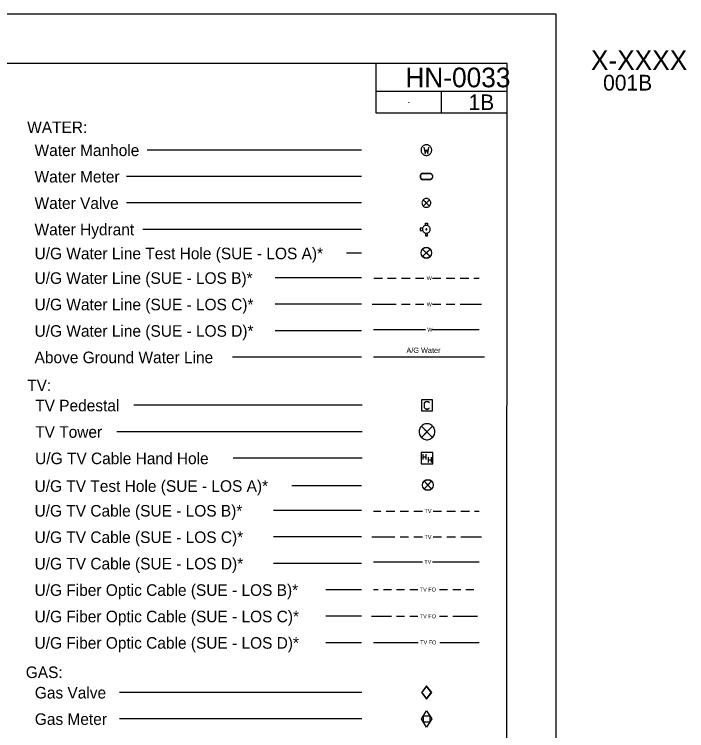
# Model space of a CAD drawing. Extents: x 0 to 3, y 0 to 1.83.
# Drawn here: x 2.143 to 3, y 0.922 to 1.833 of the extents above; entities that cross this region are included whole.
import ezdxf

# ---------------------------------------------------------------- set-up
doc = ezdxf.new("R2010")
doc.units = 0
for name, color, linetype in [('Exist Utilities TV Test Hole SUE LOS A CELL', 7, 'Continuous'), ('Old_Level_2', 7, 'Continuous'), ('Sheet_Plan', 7, 'Continuous'), ('Sheet_Symbology', 7, 'Continuous'), ('Sheet_Title_Block_Text', 7, 'Continuous'), ('z - Construction', 7, 'Continuous')]:
    doc.layers.add(name, color=color, linetype=linetype)

msp = doc.modelspace()

# ---------------------------------------------------------------- linework, layer by layer
at = {"layer": 'Exist Utilities TV Test Hole SUE LOS A CELL'}
for points in [[(2.67474, 1.2391), (2.66524, 1.22959), (2.66999, 1.23434), (2.66524, 1.2391), (2.67474, 1.22959)], [(2.66524, 1.2391), (2.66999, 1.23434), (2.67474, 1.2391)], [(2.67474, 1.22959), (2.66999, 1.23434), (2.66524, 1.22959)]]:
    msp.add_lwpolyline(points, dxfattribs=at)
msp.add_circle((2.66999, 1.23434), 0.00672, dxfattribs=at)
for start, end in [(45, 135), (225, 315)]:
    msp.add_arc((2.66999, 1.23434), 0.00672, start, end, dxfattribs=at)
at = {"layer": 'Old_Level_2'}
for points in [[(2.67282, 1.53463), (2.66332, 1.52512), (2.66807, 1.52988), (2.66332, 1.53463), (2.67282, 1.52512)], [(2.66332, 1.53463), (2.66807, 1.52988), (2.67282, 1.53463)], [(2.67282, 1.52512), (2.66807, 1.52988), (2.66332, 1.52512)]]:
    msp.add_lwpolyline(points, dxfattribs=at)
msp.add_circle((2.66807, 1.52988), 0.00672, dxfattribs=at)
for start, end in [(45, 135), (225, 315)]:
    msp.add_arc((2.66807, 1.52988), 0.00672, start, end, dxfattribs=at)
at = {"layer": 'Sheet_Plan'}
for p, q in [((2.77083, 1.77083), (0.06249, 1.77083)), ((2.60416, 1.70763), (2.60416, 1.77083)), ((2.77079, 0.0625), (2.77083, 1.77083)), ((2.77083, 1.73513), (2.60416, 1.73513)), ((2.68749, 1.70763), (2.6875, 1.73513)), ((2.77083, 1.70763), (2.60416, 1.70763))]:
    msp.add_line(p, q, dxfattribs=at)
msp.add_circle((2.60416, 1.70763), 0.0001, dxfattribs=at)
at = {"layer": 'Sheet_Symbology'}
for p, q in [((2.58571, 1.66059), (2.31265, 1.66059)), ((2.58571, 1.62696), (2.28633, 1.62696)), ((2.663, 1.63128), (2.67333, 1.63128)), ((2.663, 1.63094), (2.67333, 1.63094)), ((2.67326, 1.62304), (2.663, 1.62304)), ((2.67326, 1.6227), (2.663, 1.6227)), ((2.58571, 1.59333), (2.28633, 1.59333)), ((2.58571, 1.5597), (2.30693, 1.5597)), ((2.58571, 1.52928), (2.56629, 1.52928)), ((2.58571, 1.49793), (2.47577, 1.49793)), ((2.60114, 1.49756), (2.61207, 1.49756)), ((2.6188, 1.49756), (2.62973, 1.49756)), ((2.63645, 1.49756), (2.64738, 1.49756)), ((2.65411, 1.49756), (2.66504, 1.49756)), ((2.6758, 1.49756), (2.68673, 1.49756)), ((2.69346, 1.49756), (2.70439, 1.49756)), ((2.71111, 1.49756), (2.72204, 1.49756)), ((2.72877, 1.49756), (2.73539, 1.49756)), ((2.58571, 1.4643), (2.47577, 1.4643)), ((2.59923, 1.4643), (2.62973, 1.4643)), ((2.63645, 1.4643), (2.64738, 1.4643)), ((2.65411, 1.4643), (2.66504, 1.4643)), ((2.6758, 1.4643), (2.68673, 1.4643)), ((2.69346, 1.4643), (2.70439, 1.4643)), ((2.71111, 1.4643), (2.73854, 1.4643)), ((2.60087, 1.43214), (2.66695, 1.43214)), ((2.67536, 1.43214), (2.73539, 1.43214)), ((2.58571, 1.43067), (2.47577, 1.43067)), ((2.58571, 1.39703), (2.4214, 1.39703)), ((2.60087, 1.3974), (2.74214, 1.3974)), ((2.58651, 1.33575), (2.29575, 1.33575)), ((2.66788, 1.3308), (2.67004, 1.3308)), ((2.58651, 1.30212), (2.27401, 1.30212)), ((2.58651, 1.26849), (2.4222, 1.26849)), ((2.66378, 1.27358), (2.66378, 1.2668)), ((2.66378, 1.27012), (2.66765, 1.27012)), ((2.66765, 1.27358), (2.66765, 1.2668)), ((2.67025, 1.26989), (2.67025, 1.26311)), ((2.67412, 1.26989), (2.67412, 1.26311)), ((2.67025, 1.26643), (2.67412, 1.26643)), ((2.58571, 1.23329), (2.49682, 1.23329)), ((2.58571, 1.20182), (2.47358, 1.20182)), ((2.60087, 1.20127), (2.61024, 1.20127)), ((2.61697, 1.20127), (2.6279, 1.20127)), ((2.63462, 1.20127), (2.64555, 1.20127)), ((2.65228, 1.20127), (2.66321, 1.20127)), ((2.67666, 1.20127), (2.68759, 1.20127)), ((2.69432, 1.20127), (2.70525, 1.20127)), ((2.71198, 1.20127), (2.72291, 1.20127)), ((2.72963, 1.20127), (2.73539, 1.20127)), ((2.58571, 1.16819), (2.47358, 1.16819)), ((2.59854, 1.16819), (2.6279, 1.16819)), ((2.63462, 1.16819), (2.64555, 1.16819)), ((2.65228, 1.16819), (2.66321, 1.16819)), ((2.67666, 1.16819), (2.68759, 1.16819)), ((2.69432, 1.16819), (2.70525, 1.16819)), ((2.71198, 1.16819), (2.73822, 1.16819)), ((2.58571, 1.13455), (2.47358, 1.13455)), ((2.60087, 1.13659), (2.66338, 1.13659)), ((2.67599, 1.13659), (2.73539, 1.13659)), ((2.58571, 1.10092), (2.53991, 1.10092)), ((2.60087, 1.10133), (2.60675, 1.10133)), ((2.61348, 1.10133), (2.62357, 1.10133)), ((2.63029, 1.10133), (2.64038, 1.10133)), ((2.64711, 1.10133), (2.6572, 1.10133)), ((2.68494, 1.10133), (2.69503, 1.10133)), ((2.70176, 1.10133), (2.71185, 1.10133)), ((2.71858, 1.10133), (2.72866, 1.10133)), ((2.58571, 1.06729), (2.53991, 1.06729)), ((2.59811, 1.06729), (2.62357, 1.06729)), ((2.63029, 1.06729), (2.64038, 1.06729)), ((2.64711, 1.06729), (2.6572, 1.06729)), ((2.68494, 1.06729), (2.69503, 1.06729)), ((2.70176, 1.06729), (2.73326, 1.06729)), ((2.58571, 1.03366), (2.53991, 1.03366)), ((2.60087, 1.03406), (2.65768, 1.03406)), ((2.68543, 1.03406), (2.73539, 1.03406)), ((2.66847, 0.97825), (2.66256, 0.97032)), ((2.67438, 0.97032), (2.66847, 0.97825)), ((2.58606, 0.97032), (2.27751, 0.97032)), ((2.66256, 0.97032), (2.66847, 0.96238)), ((2.66847, 0.96238), (2.67438, 0.97032)), ((2.58606, 0.93669), (2.27751, 0.93669))]:
    msp.add_line(p, q, dxfattribs=at)
for points in [[(2.66813, 1.66742), (2.66725, 1.66736), (2.66644, 1.6672), (2.66562, 1.66693), (2.66485, 1.66654), (2.66414, 1.66611), (2.66349, 1.66556), (2.66288, 1.66491), (2.66239, 1.66425), (2.66196, 1.66349), (2.66168, 1.66267), (2.66146, 1.66185), (2.66136, 1.66103), (2.66136, 1.66015), (2.66146, 1.65933), (2.66168, 1.65846), (2.66196, 1.65769), (2.66239, 1.65693), (2.66288, 1.65628), (2.66349, 1.65562), (2.66414, 1.65507), (2.66485, 1.65464), (2.66562, 1.65425), (2.66644, 1.65398), (2.66731, 1.65382), (2.66813, 1.65376), (2.669, 1.65382), (2.66982, 1.65398), (2.67064, 1.65425), (2.67141, 1.65464), (2.67211, 1.65507), (2.67277, 1.65562), (2.67337, 1.65628), (2.67386, 1.65693), (2.6743, 1.65769), (2.67457, 1.65851), (2.67479, 1.65933), (2.6749, 1.66015), (2.6749, 1.66103), (2.67479, 1.66185), (2.67457, 1.66272), (2.6743, 1.66349), (2.67386, 1.66425), (2.67337, 1.66491), (2.67277, 1.66556), (2.67211, 1.66611), (2.67141, 1.66654), (2.67064, 1.66693), (2.66982, 1.6672), (2.66895, 1.66736), (2.66813, 1.66742)], [(2.66507, 1.66436), (2.66649, 1.65639), (2.66813, 1.66141), (2.66982, 1.65639), (2.67124, 1.66436)], [(2.663, 1.63128), (2.66232, 1.63094), (2.66171, 1.63047), (2.66117, 1.62986), (2.66077, 1.62926), (2.66043, 1.62851), (2.66023, 1.62777), (2.66016, 1.62703), (2.66023, 1.62622), (2.66043, 1.62547), (2.66077, 1.6248), (2.66117, 1.62412), (2.66171, 1.62358), (2.66232, 1.62311), (2.663, 1.6227)], [(2.66313, 1.63101), (2.66246, 1.63061), (2.66185, 1.63013), (2.66131, 1.62953), (2.6609, 1.62892), (2.66063, 1.62818), (2.6605, 1.62736), (2.6605, 1.62662), (2.66063, 1.62588), (2.6609, 1.62514), (2.66131, 1.62446), (2.66185, 1.62385), (2.66246, 1.62338), (2.66313, 1.62304)], [(2.67312, 1.63101), (2.67387, 1.63067), (2.67448, 1.63013), (2.67495, 1.62959), (2.67535, 1.62892), (2.67562, 1.62818), (2.67576, 1.62736), (2.67576, 1.62662), (2.67562, 1.62581), (2.67535, 1.62514), (2.67495, 1.62446), (2.67441, 1.62385), (2.6738, 1.62338), (2.67312, 1.62297)], [(2.67326, 1.63128), (2.67394, 1.63094), (2.67454, 1.63047), (2.67508, 1.62986), (2.67549, 1.62926), (2.67583, 1.62851), (2.67603, 1.62777), (2.6761, 1.62703), (2.67603, 1.62622), (2.67583, 1.62547), (2.67549, 1.6248), (2.67508, 1.62412), (2.67454, 1.62358), (2.67394, 1.62311), (2.67326, 1.6227)], [(2.67371, 1.59333), (2.67365, 1.59413), (2.67347, 1.595), (2.67316, 1.59575), (2.67272, 1.59649), (2.67222, 1.59711), (2.6716, 1.59767), (2.67092, 1.59817), (2.67018, 1.59854), (2.66937, 1.59879), (2.66856, 1.59891), (2.66769, 1.59891), (2.66689, 1.59879), (2.66608, 1.59854), (2.66533, 1.59817), (2.66465, 1.59767), (2.66403, 1.59711), (2.66354, 1.59649), (2.6631, 1.59575), (2.66279, 1.595), (2.66261, 1.59413), (2.66254, 1.59333), (2.66261, 1.59252), (2.66279, 1.59165), (2.6631, 1.59091), (2.66354, 1.59016), (2.66403, 1.58954), (2.66465, 1.58898), (2.66533, 1.58849), (2.66608, 1.58811), (2.66689, 1.58786), (2.66769, 1.58774), (2.66856, 1.58774), (2.66937, 1.58786), (2.67018, 1.58811), (2.67092, 1.58849), (2.6716, 1.58898), (2.67222, 1.58954), (2.67272, 1.59016), (2.67316, 1.59091), (2.67347, 1.59165), (2.67365, 1.59252), (2.67371, 1.59333)], [(2.6721, 1.58936), (2.66416, 1.5973), (2.66813, 1.59333), (2.66416, 1.58936), (2.6721, 1.5973)], [(2.66335, 1.56099), (2.66013, 1.56099), (2.66013, 1.55841), (2.66335, 1.55841)], [(2.66806, 1.56467), (2.66729, 1.5646), (2.66652, 1.56441), (2.66574, 1.56409), (2.66509, 1.56363), (2.66451, 1.56312), (2.664, 1.56247), (2.66361, 1.56176), (2.66335, 1.56099), (2.66316, 1.56021), (2.66316, 1.55944), (2.66329, 1.55866), (2.66348, 1.55789), (2.66387, 1.55718), (2.66432, 1.55653), (2.6649, 1.55595), (2.66555, 1.55544), (2.66626, 1.55511), (2.66703, 1.55485), (2.66781, 1.55473), (2.66858, 1.55473), (2.66936, 1.55485), (2.67013, 1.55518), (2.67084, 1.5555), (2.67148, 1.55602), (2.672, 1.5566), (2.67245, 1.55724), (2.67278, 1.55802), (2.67303, 1.55879), (2.6731, 1.55957), (2.67303, 1.56034), (2.6729, 1.56112), (2.67258, 1.56189), (2.6722, 1.5626), (2.67168, 1.56318), (2.67103, 1.5637), (2.67039, 1.56415), (2.66961, 1.56441), (2.66884, 1.5646), (2.66806, 1.56467)], [(2.6669, 1.56454), (2.6669, 1.56776), (2.66948, 1.56776), (2.66948, 1.56447)], [(2.66813, 1.56028), (2.66787, 1.56021), (2.66768, 1.56002), (2.66755, 1.55976), (2.66761, 1.5595), (2.66774, 1.55924), (2.668, 1.55912), (2.66826, 1.55912), (2.66851, 1.55924), (2.66864, 1.5595), (2.66871, 1.55976), (2.66858, 1.56002), (2.66839, 1.56021), (2.66813, 1.56028)], [(2.6669, 1.55485), (2.6669, 1.55163), (2.66948, 1.55163), (2.66948, 1.55492)], [(2.66192, 1.32874), (2.67594, 1.32874), (2.67594, 1.34276), (2.66192, 1.34276), (2.66192, 1.32874)], [(2.67221, 1.33236), (2.67055, 1.3308), (2.66732, 1.3308), (2.66576, 1.33236), (2.66576, 1.33915), (2.66732, 1.3407), (2.67055, 1.3407), (2.67221, 1.33915)], [(2.67906, 1.30212), (2.67895, 1.30358), (2.67861, 1.30516), (2.67805, 1.30651), (2.67726, 1.30786), (2.67636, 1.30899), (2.67523, 1.31), (2.674, 1.3109), (2.67265, 1.31157), (2.67118, 1.31203), (2.66972, 1.31225), (2.66814, 1.31225), (2.66668, 1.31203), (2.66522, 1.31157), (2.66387, 1.3109), (2.66263, 1.31), (2.66151, 1.30899), (2.66061, 1.30786), (2.65982, 1.30651), (2.65925, 1.30516), (2.65892, 1.30358), (2.65881, 1.30212), (2.65892, 1.30066), (2.65925, 1.29908), (2.65982, 1.29773), (2.66061, 1.29638), (2.66151, 1.29525), (2.66263, 1.29424), (2.66387, 1.29334), (2.66522, 1.29267), (2.66668, 1.29221), (2.66814, 1.29199), (2.66972, 1.29199), (2.67118, 1.29221), (2.67265, 1.29267), (2.674, 1.29334), (2.67523, 1.29424), (2.67636, 1.29525), (2.67726, 1.29638), (2.67805, 1.29773), (2.67861, 1.29908), (2.67895, 1.30066), (2.67906, 1.30212)], [(2.67613, 1.29492), (2.66173, 1.30932), (2.66893, 1.30212), (2.66173, 1.29492), (2.67613, 1.30932)], [(2.66169, 1.26125), (2.67617, 1.26125), (2.67617, 1.27573), (2.66169, 1.27573), (2.66169, 1.26125)], [(2.66847, 0.97893), (2.66206, 0.97032), (2.66847, 0.96171), (2.67489, 0.97032), (2.66847, 0.97893)], [(2.66206, 0.93669), (2.66847, 0.94707), (2.67489, 0.93669), (2.66847, 0.92631), (2.66206, 0.93669)], [(2.66451, 0.94057), (2.67244, 0.94057), (2.67244, 0.93272), (2.66451, 0.93272), (2.66451, 0.94057)]]:
    msp.add_lwpolyline(points, dxfattribs=at)
at = {"layer": 'z - Construction'}
for p, q in [((2.83333, 1.83333), (0, 1.83333)), ((2.83333, 0), (2.83333, 1.83333))]:
    msp.add_line(p, q, dxfattribs=at)
for centre in [(2.6875, 1.75298), (2.64583, 1.72138), (2.72916, 1.72138)]:
    msp.add_circle(centre, 0.0001, dxfattribs=at)

# ---------------------------------------------------------------- texts
at = {"layer": 'Sheet_Symbology'}
for s, height, p in [('WATER:', 0.014714, (2.15982, 1.68218)), ('Water Manhole', 0.0147137, (2.16919, 1.65296)), ('Water Meter', 0.0147137, (2.16919, 1.61933)), ('Water Valve', 0.0147137, (2.16919, 1.5857)), ('Water Hydrant', 0.0147137, (2.16919, 1.55207)), ('U/G Water Line Test Hole (SUE - LOS A)*', 0.0147137, (2.16919, 1.52165)), ('U/G Water Line (SUE - LOS B)*', 0.0147137, (2.16919, 1.4903)), ('W', 0.00504, (2.66857, 1.49504)), ('U/G Water Line (SUE - LOS C)*', 0.0147137, (2.16919, 1.45667)), ('W', 0.00504, (2.66857, 1.46178)), ('U/G Water Line (SUE - LOS D)*', 0.0147137, (2.16919, 1.42304)), ('W', 0.00504, (2.66931, 1.42962)), ('Above Ground Water Line', 0.0147137, (2.16919, 1.3894)), ('A/G Water', 0.006726, (2.64278, 1.40244)), ('TV:', 0.014714, (2.15982, 1.35382)), ('TV Pedestal', 0.0147137, (2.16999, 1.32812)), ('TV Tower', 0.014714, (2.16999, 1.29449)), ('U/G TV Cable Hand Hole', 0.0147137, (2.16999, 1.26086)), ('U/G TV Test Hole (SUE - LOS A)*', 0.0147137, (2.16919, 1.22566)), ('U/G TV Cable (SUE - LOS B)*', 0.0147137, (2.16919, 1.19419)), ('TV', 0.005045, (2.66582, 1.19875)), ('U/G TV Cable (SUE - LOS C)*', 0.0147137, (2.16919, 1.16056)), ('TV', 0.005045, (2.66582, 1.16566)), ('U/G TV Cable (SUE - LOS D)*', 0.0147137, (2.16919, 1.12692)), ('TV', 0.005045, (2.66556, 1.13407)), ('U/G Fiber Optic Cable (SUE - LOS B)*', 0.0147137, (2.16919, 1.09329)), ('TV FO', 0.005045, (2.6598, 1.09881)), ('U/G Fiber Optic Cable (SUE - LOS C)*', 0.0147137, (2.16919, 1.05966)), ('TV FO', 0.005045, (2.6598, 1.06477)), ('U/G Fiber Optic Cable (SUE - LOS D)*', 0.0147137, (2.16919, 1.02603)), ('TV FO', 0.005045, (2.66029, 1.03153)), ('GAS:', 0.014714, (2.15798, 0.98869)), ('Gas Valve', 0.014714, (2.16953, 0.96269)), ('Gas Meter', 0.014714, (2.16953, 0.92906))]:
    msp.add_text(s, height=height, dxfattribs=at).set_placement(p)
at = {"layer": 'Sheet_Title_Block_Text'}
for s, height, p in [('X-XXXX', 0.025, (2.87771, 1.76252)), ('HN-0033', 0.025, (2.6414, 1.74048)), ('001B', 0.02, (2.89321, 1.73635)), ('1B', 0.02, (2.72181, 1.71138))]:
    msp.add_text(s, height=height, dxfattribs=at).set_placement(p)

doc.saveas('drawing.dxf')
